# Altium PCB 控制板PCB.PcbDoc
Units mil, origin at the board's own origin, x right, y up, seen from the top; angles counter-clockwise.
Board outline 3952.04 x 3955.04 mil, 2 copper layers (Top Layer, Bottom Layer); 17 components, 47 nets, 230 pads, 243 vias.
Unrouted connection lines stored in the file: 41.
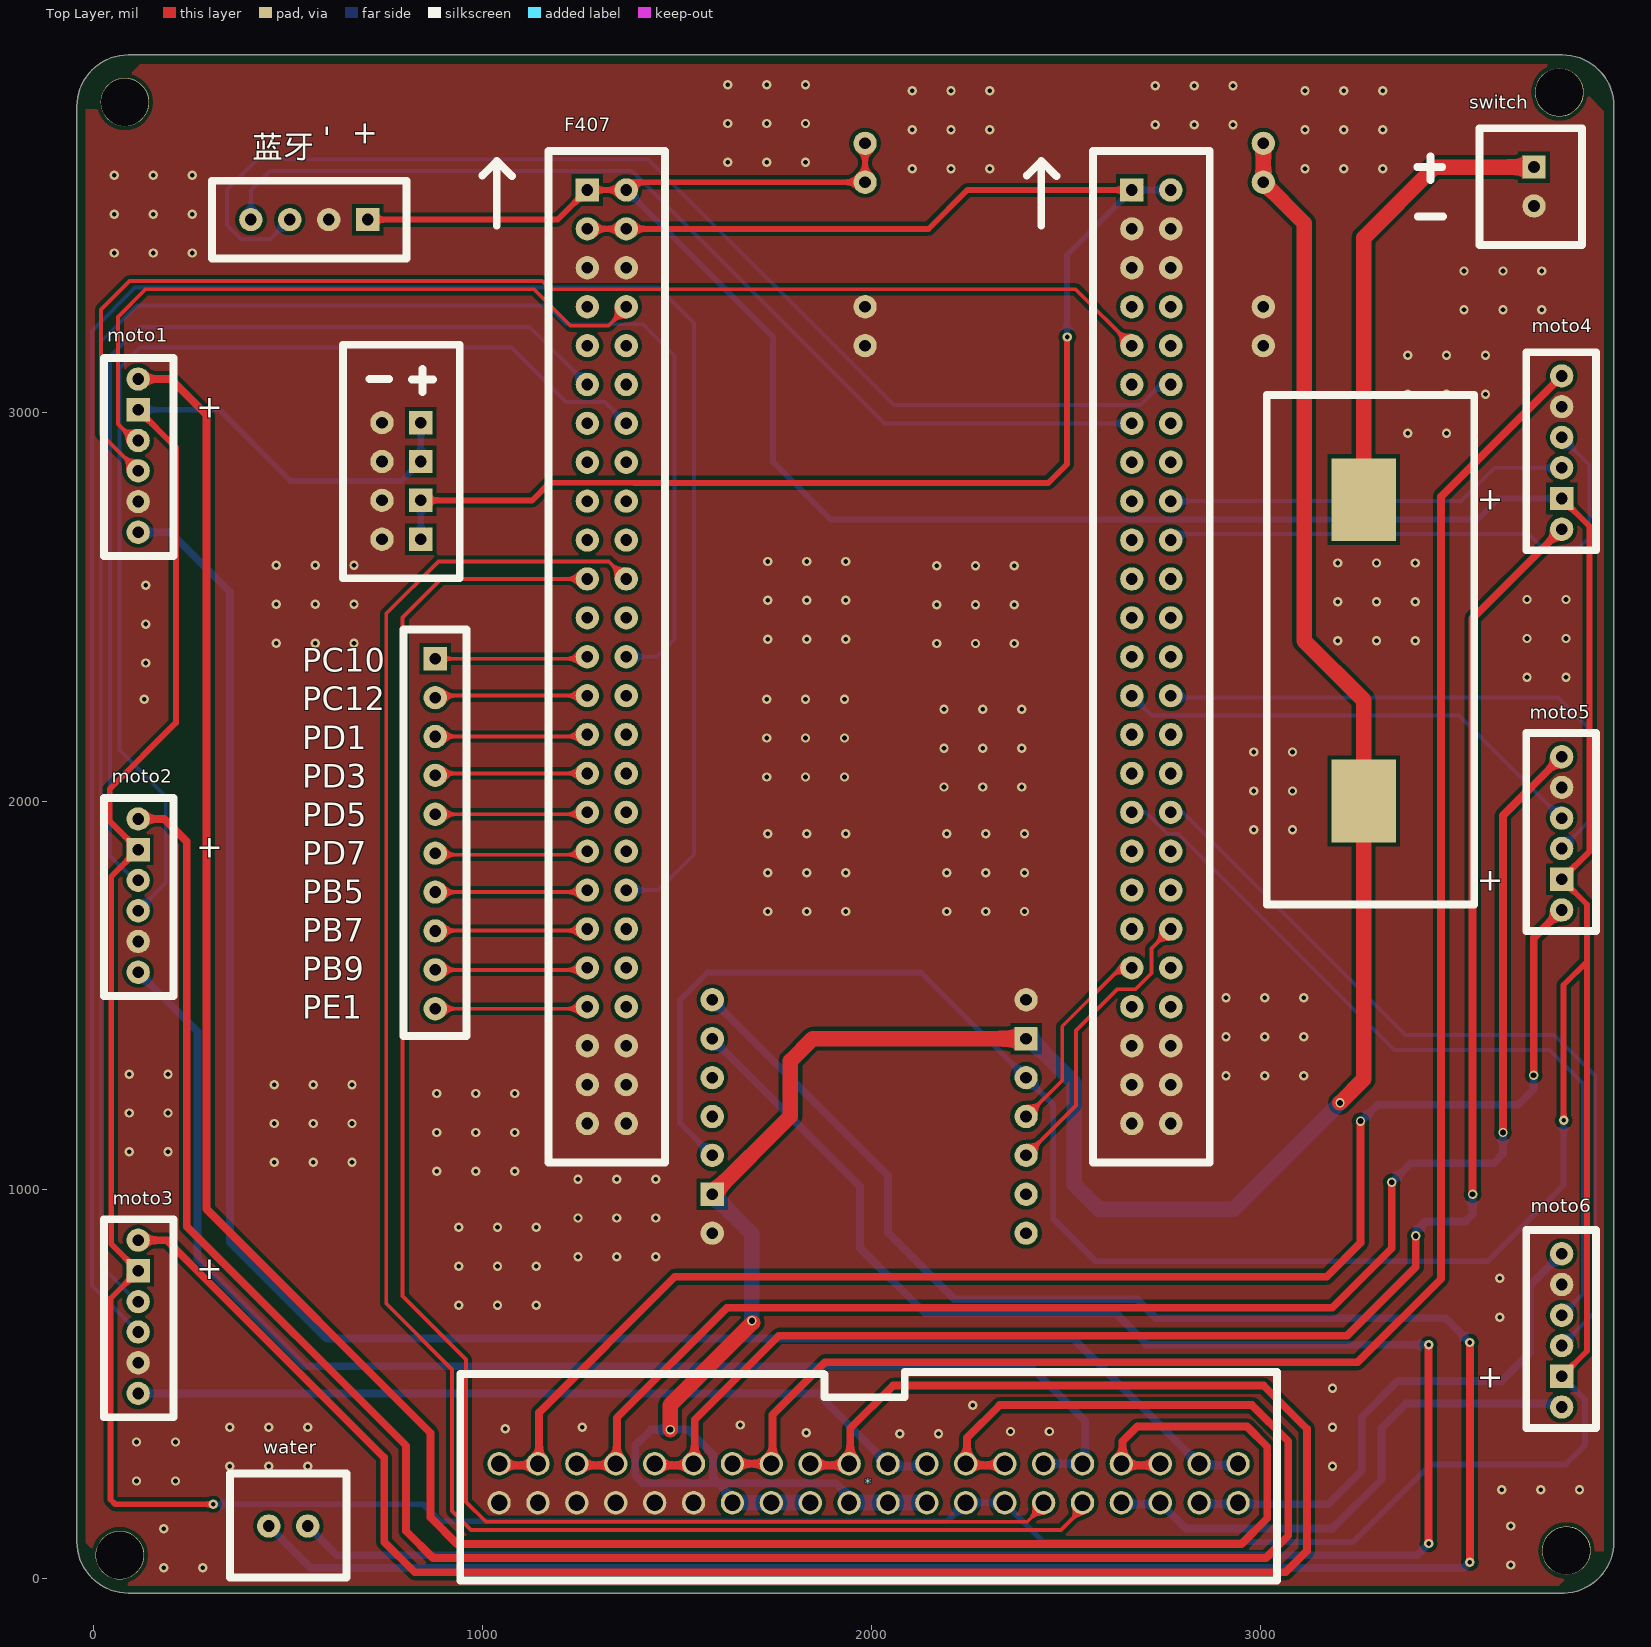
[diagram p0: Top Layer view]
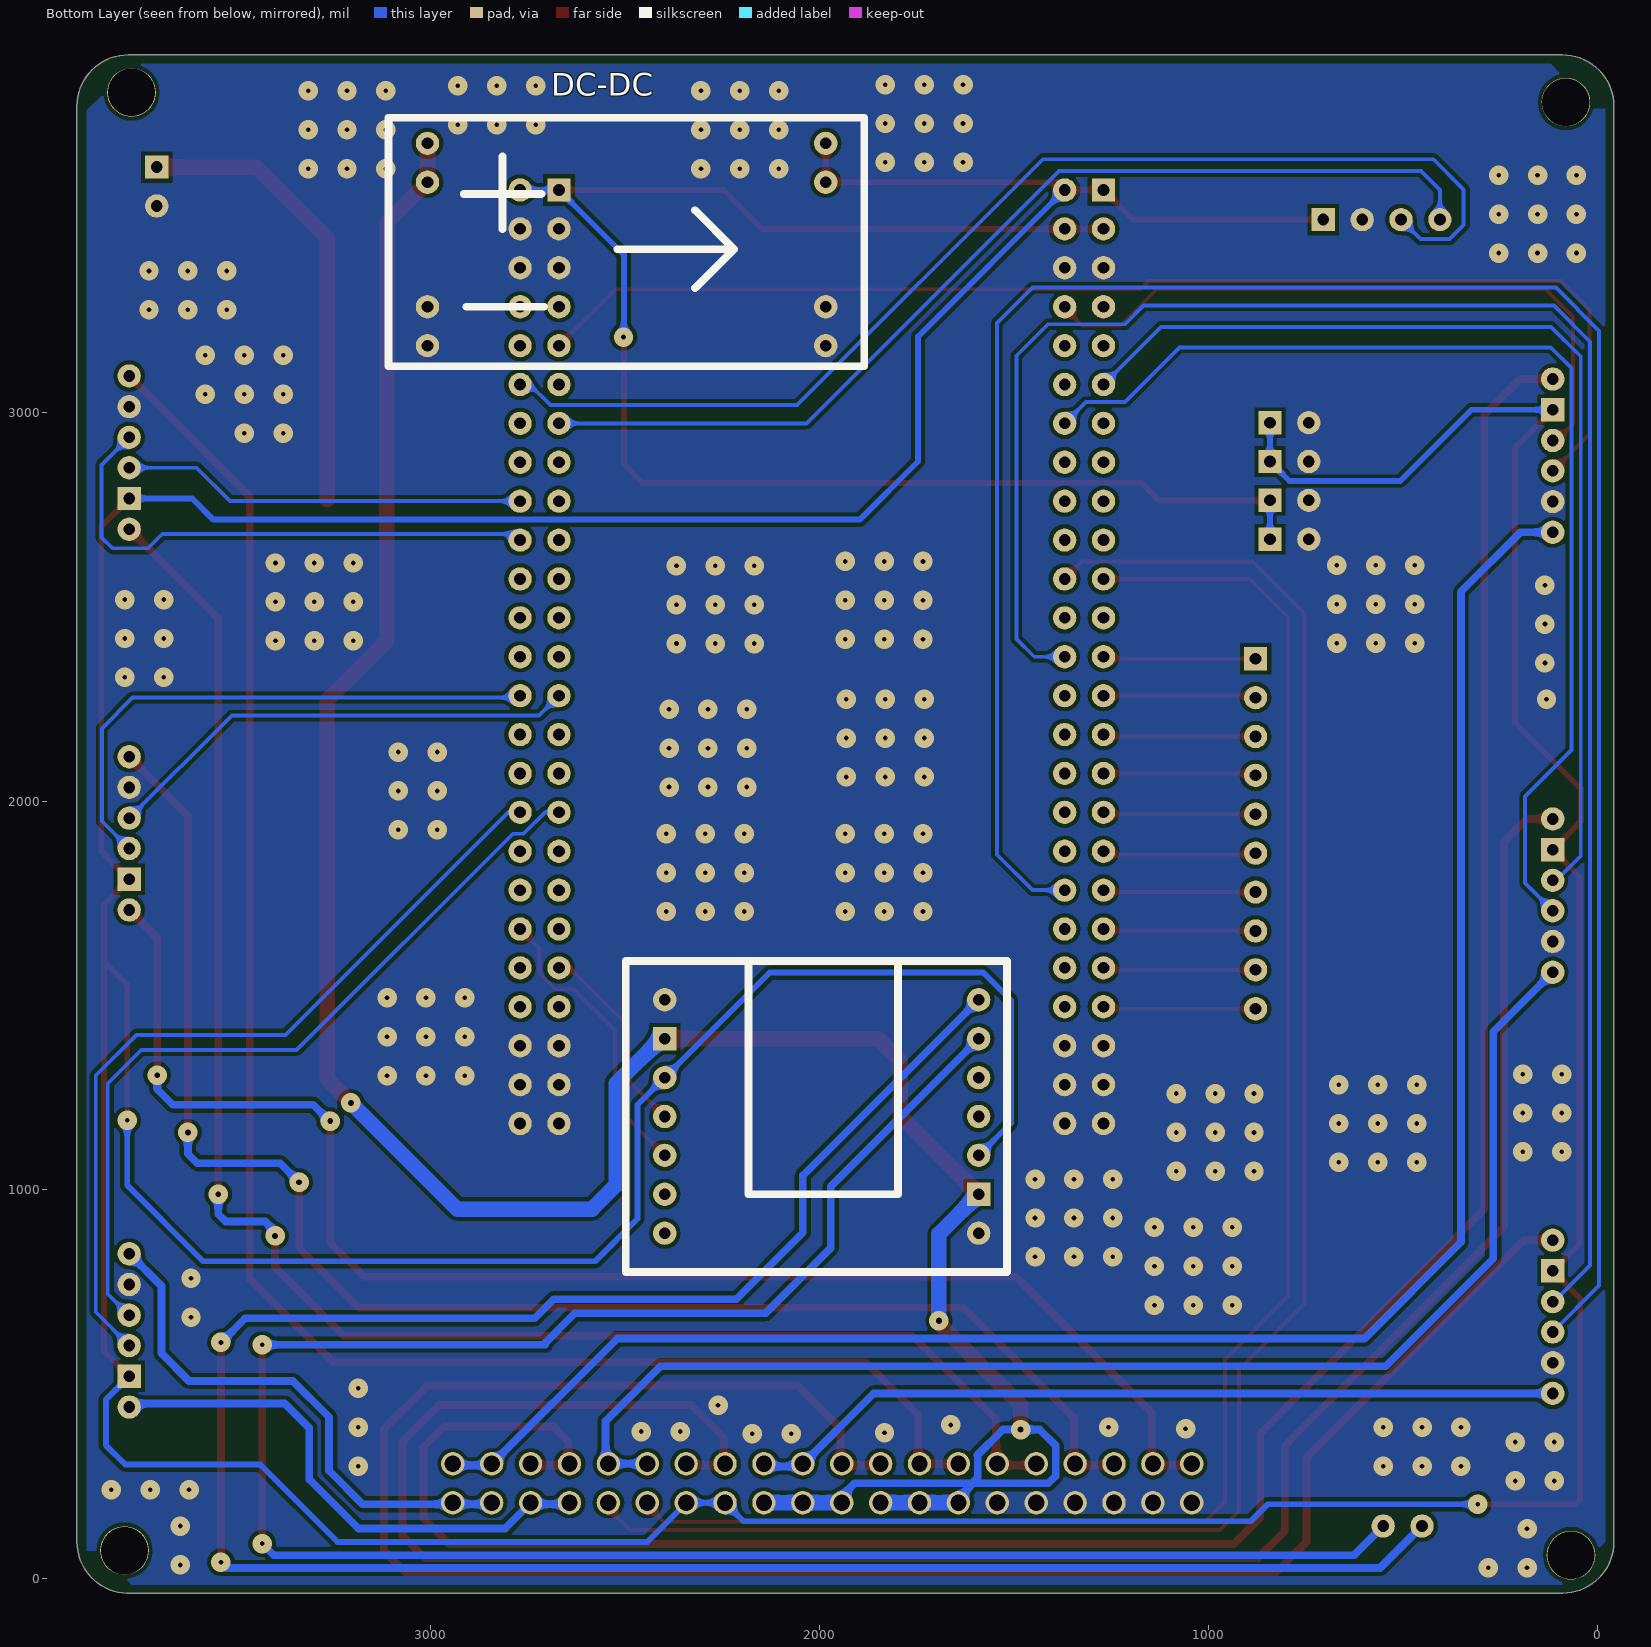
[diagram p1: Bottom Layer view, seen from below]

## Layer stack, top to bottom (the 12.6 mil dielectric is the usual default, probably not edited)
Top Solder: solder mask 0.4, Solder Resist, Dk 3.5
Top Layer: signal copper 1.4
Dielectric 1: dielectric 12.6, FR-4, Dk 4.8
Bottom Layer: signal copper 1.4
Bottom Solder: solder mask 0.4, Solder Resist, Dk 3.5

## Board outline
89.24,-36.52 cw(c89.31,96) -43.21,96 cw(c-35.69,96) -43.21,96.04 -43.21,3786 cw(c-35.69,3786) -43.21,3786.06 ccw(c89.31,3786) -43.21,3786 -43.21,3786.06 cw(c89.31,3786) 89.31,3918.52 cw(c89.31,3911) 89.38,3918.51 3775.97,3918.51 cw(c3776.31,3911.01) 3776.31,3918.52 cw(c3776.31,3786.01) 3908.82,3786.34 cw(c3901.31,3786.01) 3908.83,3786.01 3908.83,96 cw(c3776.31,96) 3780.24,-36.46 cw(c3779.31,-29) 3779.31,-36.52 89.31,-36.52 cw(c89.31,-29)

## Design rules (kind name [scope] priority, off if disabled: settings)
Clearance [All] p1: gap=10 ignorepadtopadclearanceinfootprint=FALSE except(0: Arc-Hole Track-Hole SMDPad-Hole THPad-Hole Via-Hole Fill-Hole Poly-Hole Region-Hole Text-Hole; 3: Via-Via; 5: Arc-Arc Arc-Track Track-Track)
HoleSize [All] p1: absolutevalues=TRUE maxlimit=150 minlimit=1 maxpercent=80.000 minpercent=20.000
PolygonConnect PolygonConnect_1 [All] p1: thpad.connectstyle=Direct thpad.reliefconductorwidth=10 thpad.reliefentries=4 thpad.polygonreliefangle="90 Angle" thpad.airgapwidth=10 smdpad.connectstyle=Relief smdpad.reliefconductorwidth=10 smdpad.reliefentries=4 smdpad.polygonreliefangle="90 Angle" smdpad.airgapwidth=10 via.connectstyle=Relief via.reliefconductorwidth=10 via.reliefentries=4 via.polygonreliefangle="90 Angle" via.airgapwidth=10
PolygonConnect [All] p2: connectstyle=Direct reliefconductorwidth=10 reliefentries=4 polygonreliefangle="90 Angle" airgapwidth=10
RoutingVias [All] p1: holewidth=28 width=50 viastyle="Through Hole" minholewidth=28 minwidth=50 maxholewidth=28 maxwidth=50
SolderMaskExpansion [All] p1: expansion=4
Width Width_2 [InNet('12V')] p1: maxlimit=40 minlimit=20 preferedwidth=20
Width Width_1 [InNet('5V')] p2: maxlimit=40 minlimit=15 preferedwidth=15
Width [All] p3: maxlimit=40 minlimit=10 preferedwidth=10
29 further rules are at their usual default settings.

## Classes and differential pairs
component class 控制板原理图: *1 *2 *3 *4 *5 *6 *7 *8 *9 *10 *11 *13 *14 *15 *17

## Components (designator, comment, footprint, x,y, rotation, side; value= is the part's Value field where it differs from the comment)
* "40P" PCBComponent_1 2842.31,296 r270 top
*1 "PIN_HEADER" PIN_HEADER -9427.69,-17026 r0 top
*2 "POWER_HEADER" POWER_HEADER 841.31,3073 r0 top
*13 "STM32F407右" STM32F407左 2669.31,2471 r0 top locked
*17 "A4950" A4950 2017.31,944 r180 bottom
DC-DC "DC-DC" DC-DC 2376.31,3597 r180 bottom (schematic designator *15)
F407 "STM32F407左" STM32F407左 1269.31,2471 r0 top locked (schematic designator *14)
moto1 "ENCODER1" ENCODER1 114.31,3085 r180 top (schematic designator *8)
moto2 "ENCODER2" ENCODER1 114.31,1954 r180 top (schematic designator *9)
moto3 "ENCODER3" ENCODER1 114.31,871 r180 top (schematic designator *10)
moto4 "ENCODER4" ENCODER2 3753.31,3101 r180 top (schematic designator *5)
moto5 "ENCODER5" ENCODER2 3753.31,2122 r180 top (schematic designator *6)
moto6 "ENCODER6" ENCODER2 3753.31,844 r180 top (schematic designator *7)
switch "POWER" POWER 3703.31,3530 r0 top (schematic designator *11)
water "WATER_MOTER" WATER_HEADER 550.31,136 r90 top (schematic designator *3)
蓝牙 "HC-06" HC-06 411.31,3687 r270 top (schematic designator *12)
? "SWITCH" switch 3265.31,2775 r270 top

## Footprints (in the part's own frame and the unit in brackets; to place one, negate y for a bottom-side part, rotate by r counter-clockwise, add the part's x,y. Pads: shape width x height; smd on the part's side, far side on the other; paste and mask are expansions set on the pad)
A4950 [mil]
  round 60 hole 30: 1(-380,545) 3(-380,345) 4(-380,245) 5(-380,145) 6(-380,45) 7(-380,-55) 8(427,545) 9(427,445) 10(427,345) 11(427,245) 12(427,145) 14(427,-55)
  rect 60x60 hole 30: 2(-380,445) 13(427,45)
  silkscreen extent -480,-155 500,645
DC-DC [mil]
  round 60 hole 30: 1(-631,-426) 2(-631,-326) 3(-631,-6) 4(-631,94) 5(393,-426) 6(393,-326) 7(393,-6) 8(393,94)
  silkscreen extent -731,-479 492,160
ENCODER1 [mil]
  round 60 hole 30: 1(0,394) 2(0,315) 3(0,236) 4(0,158) 6(0,0)
  rect 60x60 hole 30: 5(0,79)
  silkscreen extent -91,-54 88,455
ENCODER2 [mil]
  round 60 hole 30: 1(-21,8) 2(-21,87) 3(-21,166) 4(-21,244) 6(-21,402)
  rect 60x60 hole 30: 5(-21,323)
  silkscreen extent -109,-53 70,456
HC-06 [mil]
  round 60 hole 30: 1(192,-7) 2(192,93) 3(192,193)
  rect 60x60 hole 30: 4(192,293)
  silkscreen extent 92,-107 292,393
PCBComponent_1 [mil]
  round 60 hole 41.73: 1(0,100) 2(0,0) 3(0,-100) 4(0,-200) 5(0,-300) 6(0,-400) 7(0,-500) 8(0,-600) 9(0,-700) 10(0,-800) 11(0,-900) 12(0,-1000) 13(0,-1100) 14(0,-1200) 15(0,-1300) 16(0,-1400) 17(0,-1500) 18(0,-1600) 19(0,-1700) 21(100,100) 22(100,0) 23(100,-100) 24(100,-200) 25(100,-300) 26(100,-400) 27(100,-500) 28(100,-600) 29(100,-700) 30(100,-800) 31(100,-900) 32(100,-1000) 33(100,-1100) 34(100,-1200) 35(100,-1300) 36(100,-1400) 37(100,-1500) 38(100,-1600) 39(100,-1700)
  round 60 hole 42.52: 20(0,-1800) 40(100,-1800)
  silkscreen extent -236,-1900 300,200
PIN_HEADER [mil]
  rect 60x60 hole 30: 1(10306,19392)
  round 60 hole 30: 2(10306,19292) 3(10306,19192) 4(10306,19092) 5(10306,18992) 6(10306,18892) 7(10306,18792) 8(10306,18692) 9(10306,18592) 10(10306,18492)
  silkscreen extent 10224,18422 10386,19467
POWER [mil]
  rect 60x60 hole 30: 1(0,100)
  round 60 hole 30: 2(0,0)
  silkscreen extent -300,-100 123,200
POWER_HEADER [mil]
  rect 60x60 hole 30: 1(0,-100) 2(0,-200) 3(0,-300) 4(0,-400)
  round 60 hole 30: 5(-100,-100) 6(-100,-200) 7(-100,-300) 8(-100,-400)
  silkscreen extent -200,-500 100,100
STM32F407左 [mil]
  rect 60x60 hole 30: 1(0,1100)
  round 60 hole 30: 2(0,1000) 3(0,900) 4(0,800) 5(0,700) 6(0,600) 7(0,500) 8(0,400) 9(0,300) 10(0,200) 11(0,100) 12(0,0) 13(0,-100) 14(0,-200) 15(0,-300) 16(0,-400) 17(0,-500) 18(0,-600) 19(0,-700) 20(0,-800) 21(0,-900) 22(0,-1000) 23(100,1100) 24(100,1000) 25(100,900) 26(100,800) 27(100,700) 28(100,600) 29(100,500) 30(100,400) 31(100,300) 32(100,200) 33(100,100) 34(100,0) 35(100,-100) 36(100,-200) 37(100,-300) 38(100,-400) 39(100,-500) 40(100,-600) 41(100,-700) 42(100,-800) 43(100,-900) 44(100,-1000) 45(0,-1100) 46(0,-1200) 47(0,-1300) 48(100,-1100) 49(100,-1200) 50(100,-1300)
  silkscreen extent -270,-1400 200,1200
switch [mm]
  rect 5.4x4.2 smd: 1(0,0) 2(19.685,0)
  silkscreen extent -6.83,-6.32 26.44,7.21
WATER_HEADER [mil]
  round 60 hole 30: 1(0,100) 2(0,0)
  silkscreen extent -132,-100 135,200

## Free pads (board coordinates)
  round 125 hole 122: 2(67.31,61) 2(80.31,3797) 2(3768.31,3822) 2(3786.31,73)

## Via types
v1: diameter 24/50 (per signal layer), hole 12, Top Layer to Bottom Layer, 234 vias
v2: diameter 24/50 (per signal layer), hole 15, Top Layer to Bottom Layer, 6 vias
v3: diameter 24/50 (per signal layer), hole 16, Top Layer to Bottom Layer, 3 vias

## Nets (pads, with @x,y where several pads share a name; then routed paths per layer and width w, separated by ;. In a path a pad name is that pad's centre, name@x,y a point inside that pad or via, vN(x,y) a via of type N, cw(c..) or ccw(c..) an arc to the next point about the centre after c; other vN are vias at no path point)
3V3: *2.3 *2.4 *13.1 *13.23 F407.2 F407.24 | length 4117.9
  Top Layer w15: *2.3 1127.31,2773 1172.81,2818.5 1388.98,2818.5 1389.48,2818 2454.31,2818 2502.31,2866 v1@2502.31,3195 ; F407.2 F407.24 2146.31,3471 2246.31,3571 *13.1
  Bottom Layer w15: *2.4 *2.3 ; v1(2503.31,3193) 2502.31,3194 2502.31,3404 *13.1 *13.23
5V: *2.1 *2.2 *17.3 *17.12 *.27 *.28 DC-DC.7 DC-DC.8 F407.1 F407.23 moto1.5 moto2.5 moto3.5 moto4.5 moto5.5 moto6.5 蓝牙.4 | length 18780.9
  Top Layer w15: moto1.5 211.31,2909 211.31,2201 41.31,2031 41.31,1948 moto2.5 45.31,1806 45.31,861 moto3.5 43.31,721 43.31,204 55.31,192 v1(307.31,192) ; 蓝牙.4 1193.31,3495 F407.1 F407.23 1389.31,3591 DC-DC.7 1983.31,3690 1982.31,3691 DC-DC.8 ; moto6.5 3839.31,586 3839.31,1587 ; moto4.5 3846.31,2706 3846.31,1871 moto5.5 3839.31,1734 3839.31,1587 ; v1(3779.31,1179) 3779.31,1527 3839.31,1587
  Bottom Layer w15: moto1.5 323.31,3006 506.31,2823 791.31,2823 *2.2 *2.1 ; v1(307.31,192) 847.31,192 890.81,148.5 2194.81,148.5 *.28 *.27 ; F407.23 1746.31,3194 1746.31,2873 1895.81,2723.5 2688.98,2723.5 2689.48,2724 2749.13,2724 2749.63,2723.5 3557.81,2723.5 3612.31,2778 moto4.5 ; *17.12 1507.31,1172 1507.31,1488 1578.31,1559 2127.31,1559 *17.3 2467.31,1219 2467.31,926 2576.31,817 3584.31,817 3779.31,1012 v1(3779.31,1179) ; *.27@2345.31,192 2442.31,95 3238.31,95 3437.31,294 3784.31,294 3834.31,344 3834.31,461 moto6.5
12V: *17.2 *17.13 *.29 *.30 *.31 *.32 *.33 *.34 ?.2 DC-DC.3 DC-DC.4 | length 7093.1
  Top Layer w40: v3(1482.31,384) 1482.31,447 v3@1694.31,659 ; *17.13 1791.31,1190 1791.31,1332 1848.31,1389 *17.2 ; DC-DC.4 DC-DC.3 3112.31,3486 3112.31,2412 3265.31,2259 ?.2 3265.31,1285 v3(3204.31,1224)
  Bottom Layer w20: *.34 1642.31,208 1604.31,246 1411.31,246 1392.31,265 1392.31,343 1433.31,384 v3(1482.31,384) 1528.02,384 1593.31,318.71 1592.31,317.71 1592.31,261 1607.31,246 1909.31,246 1942.31,213 *.31 ; *17.2 *17.2@2407.31,1389
  Bottom Layer w40: *17.13 1692.31,887 v3(1692.31,664) ; *.34 *.33 *.32 ; *.31 *.30 *.29 ; *17.2@2407.31,1389 2521.31,1275 2521.31,1014 2584.31,951 2931.31,951 v3(3204.31,1224)
12V_IN: ?.1 switch.1 | length 1186.4
  Top Layer w40: ?.1 3265.31,3448 3447.31,3630 switch.1
401R: *.25 F407.33 | length 4744.5
  Top Layer w10: F407.33 1324.31,2616 886.31,2616 752.31,2482 752.31,708 921.31,539 921.31,175 970.31,126 2487.31,126 2545.31,184 *.25@2545.31,192
401T: *.26 F407.11 | length 4385.3
  Top Layer w10: F407.11 893.31,2571 794.31,2472 794.31,727 957.31,564 957.31,198 1008.31,147 2400.31,147 *.26@2445.31,192
EN1A: F407.26 moto1.4 | length 1742.8
  Top Layer w10: moto1.4 104.31,2927 62.31,2969 62.31,3245 133.31,3316 1132.31,3316 1226.31,3222 1323.31,3222 1369.31,3268 F407.26
EN1B: *13.5 moto1.3 | length 3203.3
  Top Layer w10: moto1.3 19.31,2944 19.31,3264 92.31,3337 1153.31,3337 1174.31,3316 2524.31,3316 *13.5
EN2A: F407.6 moto2.4 | length 2701.6
  Bottom Layer w10: moto2.4@113.81,1795.5 105.81,1795.5 42.31,1859 42.31,3143 118.31,3219 1121.31,3219 F407.6
EN2B: F407.29 moto2.3 | length 2879.4
  Bottom Layer w10: moto2.3 185.31,1789 185.31,2012 66.31,2131 66.31,3113 119.31,3166 1074.31,3166 1214.31,3026 1314.31,3026 F407.29
EN3A: F407.35 moto3.4 | length 4914.8
  Bottom Layer w10: 90.31,734 18.3,806 18.31,3181 111.31,3274 1166.31,3274 1214.31,3226 1412.31,3226 1493.31,3145 1493.31,2417 1447.31,2371 F407.35
EN3B: F407.41 moto3.3 | length 5833.7
  Bottom Layer w10: moto3.3 -4.69,754 -4.69,3209 106.31,3320 1452.31,3320 1543.31,3229 1543.31,1862 1452.31,1771 F407.41
EN4A: *13.31 moto4.4 | length 1015
  Bottom Layer w10: *13.31 3515.31,2771 3601.31,2857 moto4.4@3748.67,2857
EN4B: *13.32 moto4.3 | length 1396
  Bottom Layer w10: *13.32 2785.31,2687 3689.31,2687 3726.31,2650 3817.31,2650 3845.31,2678 3845.31,2864 moto4.3
EN5A: *13.36 moto5.4 | length 1457.8
  Bottom Layer w10: *13.36 2764.31,2266 3765.31,2266 3844.31,2187 3844.31,1948 moto5.4
EN5B: *13.14 moto5.3 | length 1235.5
  Bottom Layer w10: *13.14 2720.31,2220 3510.31,2220 moto5.3
EN6A: *13.39 moto6.4 | length 2101
  Bottom Layer w10: *13.39 2800.31,1971 3372.31,1399 3755.31,1399 3860.31,1294 3860.31,686 moto6.4
EN6B: *13.17 moto6.3 | length 2067.5
  Bottom Layer w10: *13.17 2705.31,1971 2760.31,1916 2787.95,1916 3343.95,1360 3743.31,1360 3829.31,1274 3829.31,733 moto6.3
GND: *2.5 *2.6 *2.7 *2.8 *13.2 *13.3 *13.24 *13.25 *13.45 *13.46 *13.47 *13.48 *13.49 *13.50 *17.1 *17.14 *.35 *.36 *.37 *.38 *.39 *.40 DC-DC.1 DC-DC.2 DC-DC.5 DC-DC.6 F407.3 F407.25 F407.45 F407.46 F407.47 F407.48 F407.49 F407.50 moto1.2 moto2.2 moto3.2 moto4.2 moto5.2 moto6.2 switch.2 蓝牙.3
  other v1: 180.31,29 280.31,29 3643.31,36 180.31,129 3643.31,136 3620.31,229 3720.31,229 3820.31,229 110.31,252 210.31,252 350.31,290 450.31,290 550.31,290 3185.31,290 110.31,352 210.31,352 2072.31,373 2172.31,373 1832.31,376 2357.31,379 2457.31,379 1058.31,386 350.31,390 450.31,390 550.31,390 1256.31,390 3185.31,390 1662.31,396 2260.31,447 3185.31,490 3615.31,673 938.31,704 1038.31,704 1138.31,704 3615.31,773 938.31,804 1038.31,804 1138.31,804 1245.31,828 1345.31,828 1445.31,828 938.31,904 1038.31,904 1138.31,904 1245.31,928 1345.31,928 1445.31,928 1245.31,1028 1345.31,1028 1445.31,1028 882.31,1048 982.31,1048 1082.31,1048 464.31,1071 564.31,1071 664.31,1071 91.31,1098 191.31,1098 882.31,1148 982.31,1148 1082.31,1148 464.31,1171 564.31,1171 664.31,1171 91.31,1198 191.31,1198 882.31,1248 982.31,1248 1082.31,1248 464.31,1271 564.31,1271 664.31,1271 2911.31,1294 3011.31,1294 3111.31,1294 91.31,1298 191.31,1298 2911.31,1394 3011.31,1394 3111.31,1394 2911.31,1494 3011.31,1494 3111.31,1494 1733.31,1716 1833.31,1716 1933.31,1716 2193.31,1716 2293.31,1716 2393.31,1716 1733.31,1816 1833.31,1816 1933.31,1816 2193.31,1816 2293.31,1816 2393.31,1816 1733.31,1916 1833.31,1916 1933.31,1916 2193.31,1916 2293.31,1916 2393.31,1916 2982.31,1926 3082.31,1926 2982.31,2026 3082.31,2026 2186.31,2036 2286.31,2036 2386.31,2036 1730.31,2062 1830.31,2062 1930.31,2062 2982.31,2126 3082.31,2126 2186.31,2136 2286.31,2136 2386.31,2136 1730.31,2162 1830.31,2162 1930.31,2162 2186.31,2236 2286.31,2236 2386.31,2236 130.31,2262 1730.31,2262 1830.31,2262 1930.31,2262 3685.31,2318 3785.31,2318 134.31,2355 2167.31,2405 2267.31,2405 2367.31,2405 469.31,2406 569.31,2406 669.31,2406 3198.31,2412 3298.31,2412 3398.31,2412 1733.31,2416 1833.31,2416 1933.31,2416 3685.31,2418 3785.31,2418 134.31,2455 2167.31,2505 2267.31,2505 2367.31,2505 469.31,2506 569.31,2506 669.31,2506 3198.31,2512 3298.31,2512 3398.31,2512 1733.31,2516 1833.31,2516 1933.31,2516 3685.31,2518 3785.31,2518 134.31,2555 2167.31,2605 2267.31,2605 2367.31,2605 469.31,2606 569.31,2606 669.31,2606 3198.31,2612 3298.31,2612 3398.31,2612 1733.31,2616 1833.31,2616 1933.31,2616 3378.31,2946 3478.31,2946 3378.31,3046 3478.31,3046 3578.31,3046 3378.31,3146 3478.31,3146 3578.31,3146 3523.31,3263 3623.31,3263 3723.31,3263 3523.31,3363 3623.31,3363 3723.31,3363 53.31,3409 153.31,3409 253.31,3409 53.31,3509 153.31,3509 253.31,3509 53.31,3609 153.31,3609 253.31,3609 2104.31,3626 2204.31,3626 2304.31,3626 3114.31,3626 3214.31,3626 3314.31,3626 1630.31,3642 1730.31,3642 1830.31,3642 2104.31,3726 2204.31,3726 2304.31,3726 3114.31,3726 3214.31,3726 3314.31,3726 2729.31,3739 2829.31,3739 2929.31,3739 1630.31,3742 1730.31,3742 1830.31,3742 2104.31,3826 2204.31,3826 2304.31,3826 3114.31,3826 3214.31,3826 3314.31,3826 2729.31,3839 2829.31,3839 2929.31,3839 1630.31,3842 1730.31,3842 1830.31,3842
H1: *1.1 F407.13 | length 393.1
  Top Layer w10: *1.1 1264.31,2366 F407.13
H2: *1.2 F407.14 | length 393.1
  Top Layer w10: *1.2 883.31,2271 F407.14
H3: *1.3 F407.15 | length 393.1
  Top Layer w10: *1.3 1264.31,2166 F407.15
H4: *1.4 F407.16 | length 393.1
  Top Layer w10: *1.4 883.31,2071 F407.16
H5: *1.5 F407.17 | length 386
  Top Layer w10: *1.5@893.31,1966 F407.17@1279.31,1966
H6: *1.6 F407.18 | length 393.1
  Top Layer w10: *1.6@883.31,1862 F407.18@1269.31,1862 ; F407.18@1264.31,1876 F407.18
H7: *1.7 F407.19 | length 386
  Top Layer w10: *1.7@880.31,1766 F407.19@1266.31,1766
H8: *1.8 F407.20 | length 386
  Top Layer w10: *1.8@884.31,1667 F407.20@1270.31,1667
H9: *1.9 F407.21 | length 393.1
  Top Layer w10: *1.9 1264.31,1566 F407.21
H10: *1.10 F407.22 | length 393.1
  Top Layer w10: *1.10 1264.31,1466 F407.22
HR: *13.7 蓝牙.1 | length 2630.1
  Bottom Layer w10: 蓝牙.1 404.31,3571 453.31,3620 1383.94,3620 2032.94,2971 *13.7
HT: *13.28 蓝牙.2 | length 3029.7
  Bottom Layer w10: 蓝牙.2 454.31,3445 379.31,3445 343.31,3481 343.31,3572 421.31,3650 1425.31,3650 2057.31,3018 2691.31,3018 2744.31,3071 2757.31,3071 *13.28
MO11: *.1 *.2 moto1.1 | length 4804.1
  Bottom Layer w20: moto1.1 197.31,2691 350.31,2538 350.31,866 598.31,618 2519.31,618 2845.31,292 *.1@2945.31,292
MO12: *.3 *.4 moto1.6 | length 6249.5
  Top Layer w20: moto1.6 198.31,3085 290.31,2993 290.31,951 866.31,375 866.31,158 934.31,90 2951.31,90 3017.31,156 3017.31,340 2965.31,392 2683.31,392 2645.31,354 2645.31,292 *.3@2745.31,292
MO21: *.5 *.6 moto2.1 | length 3494.7
  Top Layer w20: moto2.1 moto2.1@119.31,1555
  Bottom Layer w20: moto2.1 267.31,1407 267.31,823 543.31,547 2408.31,547 2549.31,406 2549.31,289 *.5@2541.31,281 ; *.6 2539.31,296 2542.31,299 *.5
MO22: *.7 *.8 moto2.6 | length 5789.1
  Top Layer w20: moto2.6 181.31,1954 239.31,1896 239.31,906 803.31,342 803.31,123 872.31,54 3014.31,54 3071.31,111 3071.31,354 2978.31,447 2329.31,447 2245.31,363 2245.31,292 *.7@2345.31,292
MO31: *.9 *.10 moto3.1 | length 2108.2
  Bottom Layer w20: moto3.1 1860.31,477 2048.31,289 2133.31,289 *.9@2141.31,281
MO32: *.11 *.12 moto3.6 | length 5283.2
  Top Layer w20: moto3.6 188.31,871 747.31,312 747.31,95 825.31,17 3064.31,17 3119.31,72 3119.31,386 3008.31,497 2055.31,497 1945.31,387 1945.31,292 *.12@1845.31,292
MO41: *.13 *.14 moto4.1 | length 4543.4
  Top Layer w20: *.14 *.13 ; *.13@1745.31,292 1745.31,422 1880.31,557 3249.31,557 3464.31,772 3464.31,2783 moto4.1
MO42: *.15 *.16 moto4.6 | length 4343.9
  Top Layer w20: *.16@1445.31,292 1545.31,292 1545.31,409 1761.31,625 3222.31,625 3399.31,802 v2(3399.31,882) ; v2(3545.31,989) 3545.31,1034 ; 3545.31,1036 3545.31,2470 moto4.6
  Bottom Layer w20: v2(3399.31,882) 3399.31,894 3424.31,919 3526.31,919 3545.31,938 v2(3545.31,989)
MO51: *.17 *.18 moto5.1 | length 3964.4
  Top Layer w20: *.18@1245.31,292 1345.31,292 1345.31,414 1628.31,697 3184.31,697 3337.31,850 v2(3337.31,1020) ; v2(3623.31,1148) 3623.31,1963 moto5.1
  Bottom Layer w20: v2(3337.31,1020) 3386.31,1069 3599.31,1069 3623.31,1093 v2(3623.31,1148)
MO52: *.19 *.20 moto5.6 | length 3811.4
  Top Layer w20: *.20@1045.31,292 1145.31,292 1145.31,428 1494.31,777 3170.31,777 3257.31,864 v2(3257.31,1177) ; v2(3702.31,1295) 3702.31,1648 moto5.6
  Bottom Layer w20: v2(3257.31,1177) 3259.31,1177 3301.31,1219 3662.31,1219 3702.31,1259 v2(3702.31,1295)
MO61: *.21 *.22 moto6.1 | length 1394.9
  Bottom Layer w20: *.22@2845.31,192 2945.31,192 3174.31,192 3260.31,278 3260.31,416 3353.31,509 3620.31,509 3691.31,580 3691.31,753 moto6.1 moto6.1@3757.31,836
MO62: *.23 *.24 moto6.6 | length 1368.7
  Bottom Layer w20: *.24@2645.31,192 2745.31,192 2807.31,130 3185.31,130 3311.31,256 3311.31,388 3374.31,451 3765.31,451 moto6.6
WATER1: *13.21 *17.4 | length 511.7
  Top Layer w10: *17.4 2490.31,1282 2490.31,1421 2640.31,1571 *13.21
WATER2: *13.42 *17.5 | length 763.4
  Top Layer w10: *17.5 2525.31,1217 2525.31,1410 2631.31,1516 2677.95,1516 2719.31,1557.36 2719.31,1621 *13.42
WATERO1: *17.8 water.1 | length 6103
  Top Layer w20: v1(3538.31,43) v1(3538.31,608)
  Bottom Layer w20: water.1 558.31,28 3523.31,28 v1(3538.31,43) ; *17.8 2042.31,1037 2042.31,890 2213.31,719 2682.31,719 2731.31,670 3476.31,670 v1(3538.31,608)
WATERO2: *17.9 water.2 | length 5699.4
  Top Layer w20: v1(3432.31,91) v1(3432.31,602)
  Bottom Layer w15: 2705.31,602 2705.31,606
  Bottom Layer w20: water.2 625.31,61 3402.31,61 v1(3432.31,91) ; *17.9 1970.31,1009 1970.31,851 2138.31,683 2628.31,683 2705.31,606 ; 2705.31,602 v1(3432.31,602)
pads on no net: *13.4 *13.6 *13.8 *13.9 *13.10 *13.11 *13.12 *13.13 *13.15 *13.16 *13.18 *13.19 *13.20 *13.22 *13.26 *13.27 *13.29 *13.30 *13.33 *13.34 *13.35 *13.37 *13.38 *13.40 *13.41 *13.43 *13.44 *17.6 *17.7 *17.10 *17.11 F407.4 F407.5 F407.7 F407.8 F407.9 F407.10 F407.12 F407.27 F407.28 F407.30 F407.31 F407.32 F407.34 F407.36 F407.37 F407.38 F407.39 F407.40 F407.42 F407.43 F407.44

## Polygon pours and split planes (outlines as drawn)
GND on Top Layer "Top Layer-GND" (solid, remove dead copper, pour order 8): 119.31,3894 3762.31,3894 3882.31,3774 3882.31,71 3855.31,71 3767.31,-17 86.31,-17 86.31,-14 -20.69,93 -20.69,3779 4.31,3779
no net on Top Layer "Top Layer-No Net" (solid, pour order 2): 110.31,3885
no net on Top Layer "Top Layer-No Net 1" (solid, pour order 0): 168.31,3870
GND on Bottom Layer "Bottom Layer-GND" (solid, remove dead copper, pour order 10): 119.85,3895.57 3762.85,3895.57 3882.85,3775.57 3882.85,72.58 3855.85,72.58 3767.85,-15.43 86.85,-15.43 86.85,-12.43 -20.15,94.58 -20.15,3780.57 4.85,3780.57

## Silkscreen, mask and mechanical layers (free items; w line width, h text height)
Mechanical 1:
  lines w15: -35.69,96 ccw(c89.31,96) 89.31,-29 ; -35.69,3786 cw(c89.31,3786) 89.31,3911 ; 3776.31,-29 ccw(c3776.31,96) 3901.31,96 ; 3776.31,3911.01 cw(c3776.31,3786.01) 3901.31,3786.01
  lines w20: -35.69,96 -35.69,3786 ; 89.31,-29 3779.31,-29 ; 89.31,3911 3776.31,3911 ; 3901.31,96 3901.31,3786.01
